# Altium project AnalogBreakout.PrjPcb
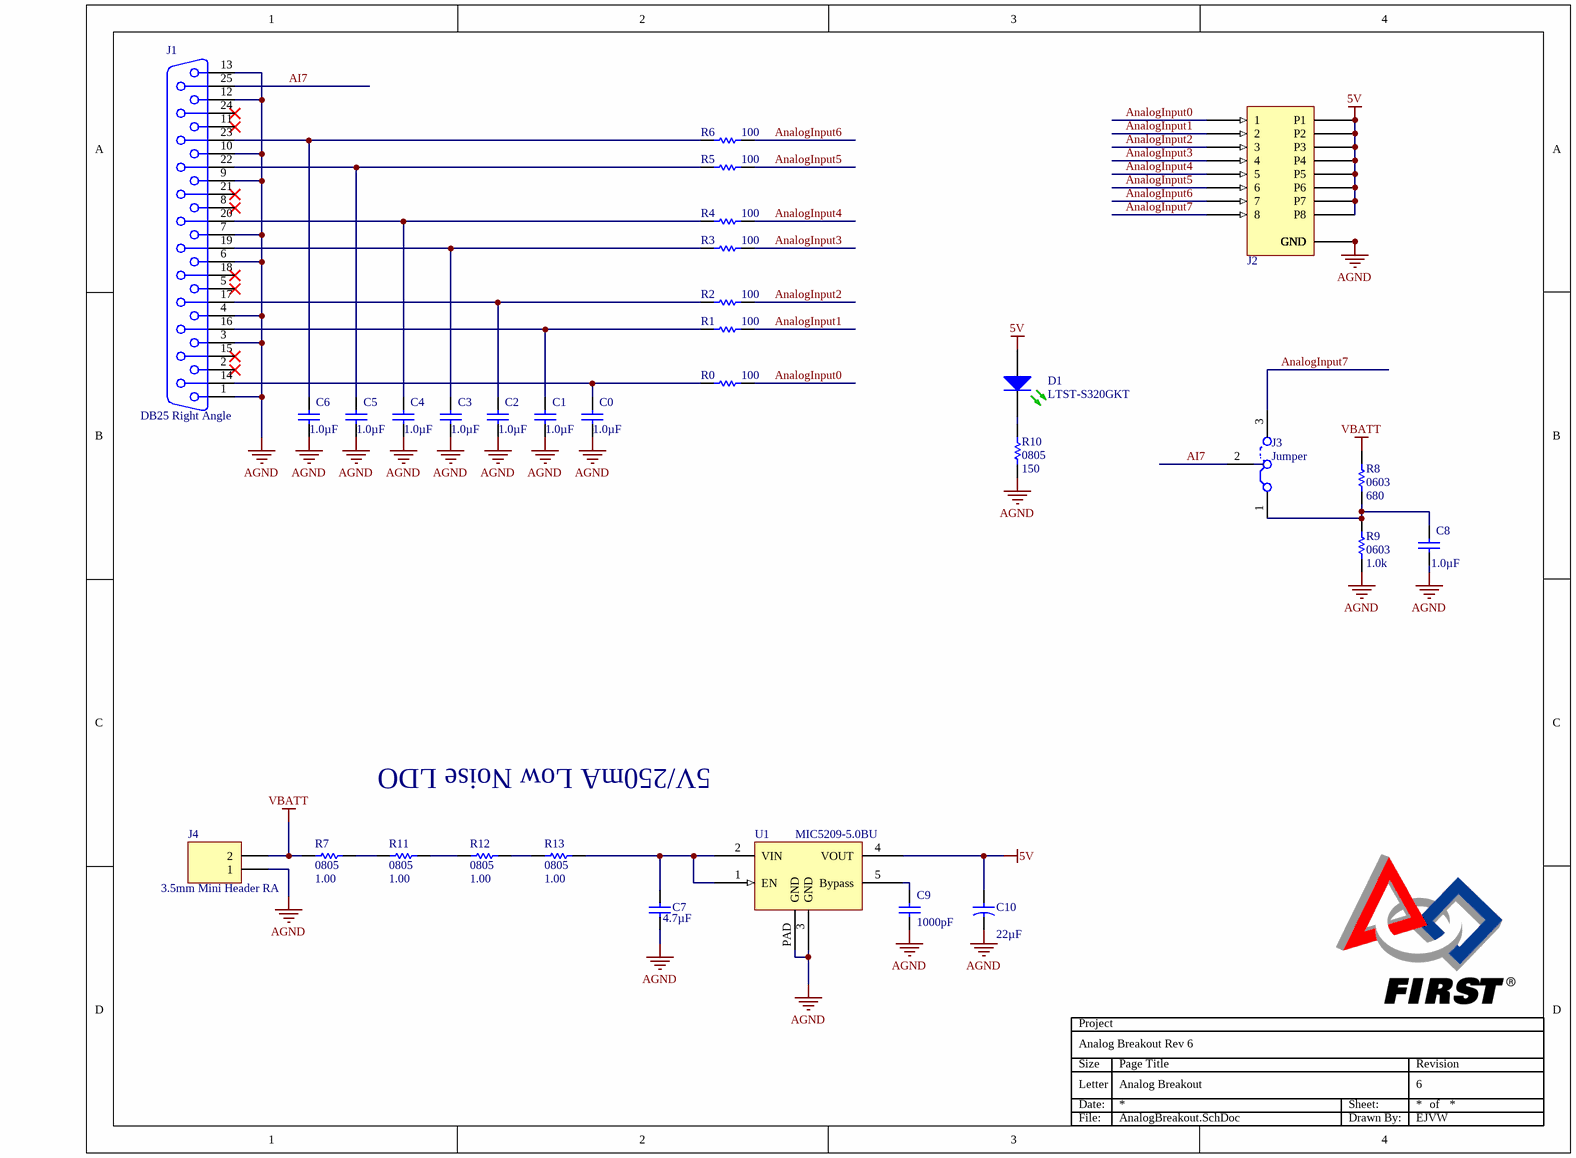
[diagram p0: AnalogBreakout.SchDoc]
ProjectTitle: Analog Breakout Rev 6
2 sheets, 31 parts. Net scope: global (net labels, ports and power ports of the same name join across sheets).
Board file: AnalogBreakout.PcbDoc
Sheets:
  AnalogBreakout.SchDoc
  Title.SchDoc

## Sheet AnalogBreakout.SchDoc: Analog Breakout
size Letter; DrawnBy: EJVW; Revision: 6

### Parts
C0  value 1.0µF  [C0603_C]  (hidden comment: 1.0 uF 0603)
C1  value 1.0µF  [C0603_C]  (hidden comment: 1.0 uF 0603)
C2  value 1.0µF  [C0603_C]  (hidden comment: 1.0 uF 0603)
C3  value 1.0µF  [C0603_C]  (hidden comment: 1.0 uF 0603)
C4  value 1.0µF  [C0603_C]  (hidden comment: 1.0 uF 0603)
C5  value 1.0µF  [C0603_C]  (hidden comment: 1.0 uF 0603)
C6  value 1.0µF  [C0603_C]  (hidden comment: 1.0 uF 0603)
C7  value 4.7µF  [C0805_C]  (hidden comment: 4.7uF 0805 25V X5R)
C8  value 1.0µF  [C0603_C]  (hidden comment: 1.0 uF 0603)
C9  value 1000pF  [C0603_C]  (hidden comment: 1000 pF 0603)
C10  value 22µF  [SMT-CAN Panasonic C]  (hidden comment: 22uF SMT 25V Elecrolytic)
D1  LTST-S320GKT  [LED1208RA LiteOn]
J1  DB25 Right Angle  [DB25 - RA]
J2  PWM_Header x8 RA  [H100P3x8RA]  (value not drawn)
J3  Jumper  [J100P3]
J4  3.5mm Mini Header RA  [WAGO 734-162]
R0  value 100  [R0603_C]  (hidden comment: 100 ohm 0603 1%)
R1  value 100  [R0603_C]  (hidden comment: 100 ohm 0603 1%)
R2  value 100  [R0603_C]  (hidden comment: 100 ohm 0603 1%)
R3  value 100  [R0603_C]  (hidden comment: 100 ohm 0603 1%)
R4  value 100  [R0603_C]  (hidden comment: 100 ohm 0603 1%)
R5  value 100  [R0603_C]  (hidden comment: 100 ohm 0603 1%)
R6  value 100  [R0603_C]  (hidden comment: 100 ohm 0603 1%)
R7  value 1.00  Footprint: 0805  [R0805_M]  (hidden comment: 1.00 ohm 0805 1%)
R8  value 680  Footprint: 0603  [R0603_C]  (hidden comment: 680 ohm 0805 1%)
R9  value 1.0k  Footprint: 0603  [R0603_C]  (hidden comment: 1.0k ohm 0603 1%)
R10  value 150  Footprint: 0805  [R0805_M]  (hidden comment: 150 ohm 0805 1%)
R11  value 1.00  Footprint: 0805  [R0805_M]  (hidden comment: 1.00 ohm 0805 1%)
R12  value 1.00  Footprint: 0805  [R0805_M]  (hidden comment: 1.00 ohm 0805 1%)
R13  value 1.00  Footprint: 0805  [R0805_M]  (hidden comment: 1.00 ohm 0805 1%)
U1  MIC5209-5.0BU  [TO-263-5]

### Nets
5V: C10.+ D1.A J2.2(P1) J2.5(P2) J2.8(P3) J2.11(P4) J2.14(P5) J2.17(P6) J2.20(P7) J2.23(P8) U1.4(VOUT)
AGND: C0.1 C1.1 C2.1 C3.1 C4.1 C5.1 C6.2 C7.1 C8.1 C9.1 C10.- J1.1 J1.3 J1.4 J1.6 J1.7 J1.9 J1.10 J1.12 J1.13 J2.3(GND) J2.6(GND) J2.9(GND) J2.12(GND) J2.15(GND) J2.18(GND) J2.21(GND) J2.24(GND) J4.1 R9.1 R10.1 U1.3(GND) U1.PAD(GND)
VBATT: J4.2 R7.1 R8.2
AI7: J1.25 J3.2
AnalogInput0: J2.1 R0.2
AnalogInput1: J2.4(2) R1.2
AnalogInput2: J2.7(3) R2.2
AnalogInput3: J2.10(4) R3.2
AnalogInput4: J2.13(5) R4.2
AnalogInput5: J2.16(6) R5.2
AnalogInput6: J2.19(7) R6.2
AnalogInput7: J2.22(8) J3.3
NetC0_2: C0.2 J1.14 R0.1
NetC1_2: C1.2 J1.16 R1.1
NetC2_2: C2.2 J1.17 R2.1
NetC3_2: C3.2 J1.19 R3.1
NetC4_2: C4.2 J1.20 R4.1
NetC5_2: C5.2 J1.22 R5.1
NetC6_1: C6.1 J1.23 R6.1
NetC7_2: C7.2 R13.2 U1.1(EN) U1.2(VIN)
NetC8_2: C8.2 J3.1 R8.1 R9.2
NetC9_2: C9.2 U1.5(Bypass)
NetD1_K: D1.K R10.2
NetR7_2: R7.2 R11.1
NetR11_2: R11.2 R12.1
NetR12_2: R12.2 R13.1

Not connected (* = marked no-connect by the designer): J1 2* 5* 8* 11* 15* 18* 21* 24*

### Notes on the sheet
- 5V/250mA Low Noise LDO

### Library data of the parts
C0-C6 C8 = 1.0µF 0603 10V: Capacitor; MFG: Kemet; MFG_PN: C0603C105K8PACTU; DIST: DigiKey; DIST_PN: 399-3118-1-ND; Tolerance: ±10%; Temperature Coefficient: X5R; Voltage: 10
C7 = 4.7uF 0805 25V X5R: CERAMIC 4.7uF 25V X5R 0805; MFG: Panasonic - ECG; MFG_PN: ECJ-2FB1E475M; DIST: DigiKey; DIST_PN: PCC2321CT-ND; Tolerance: ±20%; Voltage: 25; Checked: SCH 3/2/2008; Cost (1000): 0.08988
C9 = 1000 pF 0603 50V: Capacitor; MFG: Kemet; MFG_PN: C0603C102K5RACTU; DIST: DigiKey; DIST_PN: 399-1082-1-ND; Tolerance: ±10%; Temperature Coefficient: C0G, NP0 (COG,NPO); Voltage: 50
C10 = 22uF SMT 25V Elecrolytic: MFG: Panasonic - ECG; MFG_PN: EEV-FK1E220R; DIST: DigiKey; DIST_PN: PCE3404CT-ND; Tolerance: ±20%; Voltage: 25; ESR: 0.7; Cost (1000): 0.16950; Ripple Current (Amps): 0.160; Max Temperature (C): 105; Cost (MOQ): 0.28800
D1 = LTST-S320GKT: Green 1208RA 20mA 2V 10mcd; MFG: Panasonic - SSG; DIST: DIGIKEY; DIST_PN: 160-1206-1-ND; I_F: 20; Luminous Intensity: 12mcd; Maximum Continuous Current: 30; V_F: 2.1; Viewing Angle: 130; Cost (1000): 0.08000
J1 = DB25F RA Unthreaded: DB25F RA Unthreaded .318"; DIST: DigiKey; DIST_PN: 182-725FE-ND; MFG: Norcomp Inc.; MFG_PN: 182-025-213R161
J2 = PWM_Header x8 RA: PWM Header x8 RA; MFG: Samtec; MFG_PN: TSW-108-08-T-T-LA
J3 = Jumper 3pos 100mil_RA: Selection Jumper, Right Angle; DIST: Samtec; DIST_PN: TSW-103-08-T-S-RA
J4 = WAGO 734-162: 3.5mm Header Protected against Mismating; MFG: WAGO; Current Rating: 10 A; Mates With: 734-102/037-000
R0-R6 = 100 ohm 0603 1%: MFG: Rohm; MFG_PN: MCR03EZPFX1000; DIST: DigiKey; DIST_PN: RHM100HCT-ND; Power: 0.1; Cost (1000): 0.01595; Cost (MOQ): 0.076; BOM Note: Generic - May be replaced by equal or better part
R7 R11-R13 = 1.00 ohm 0805 1%: MFG: Rohm; MFG_PN: MCR10EZHFL1R00; DIST: DigiKey; DIST_PN: RHM1.00CCT-ND; Power: 0.25W, 1/4W; Cost (1000): 0.06830; Cost (MOQ): 0.14100
R8 = 680 ohm 0603 1%: MFG: Rohm; MFG_PN: MCR03EZPFX6800; DIST: DigiKey; DIST_PN: RHM680HCT-ND; Power: 0.1; Cost (1000): 0.01595; Cost (MOQ): 0.076; BOM Note: Generic - May be replaced by equal or better part
R9 = 1.0k ohm 0603 1%: MFG: Rohm; MFG_PN: MCR03EZPFX1001; DIST: DigiKey; DIST_PN: RHM1.00KHCT-ND; Power: 0.1; Cost (1000): 0.01595; Cost (MOQ): 0.076; BOM Note: Generic - May be replaced by equal or better part
R10 = 150 ohm 0805 1%: MFG: Rohm; MFG_PN: MCR10EZPF1500; DIST: DigiKey; DIST_PN: RHM150CRCT-ND; Power: 0.125W, 1/8W; Cost (1000): 0.01795; Cost (MOQ): 0.03700; BOM Note: Generic
U1 = MIC5209-5.0BU: 5.0V 500mA Low-Noise LDO; Current Limit: 0.500; DIST: NU Horizons; DIST_PN: MIC5209-5.0BU TR; MFG: Micrel; Voltage Output: 5.0; Maximum Drop Out Voltage: 0.600; Max Voltage: 16.0V; Topology: Linear (Fixed); Cost (1000): 1.2900

## Sheet Title.SchDoc
size Letter; SheetNumber: 1
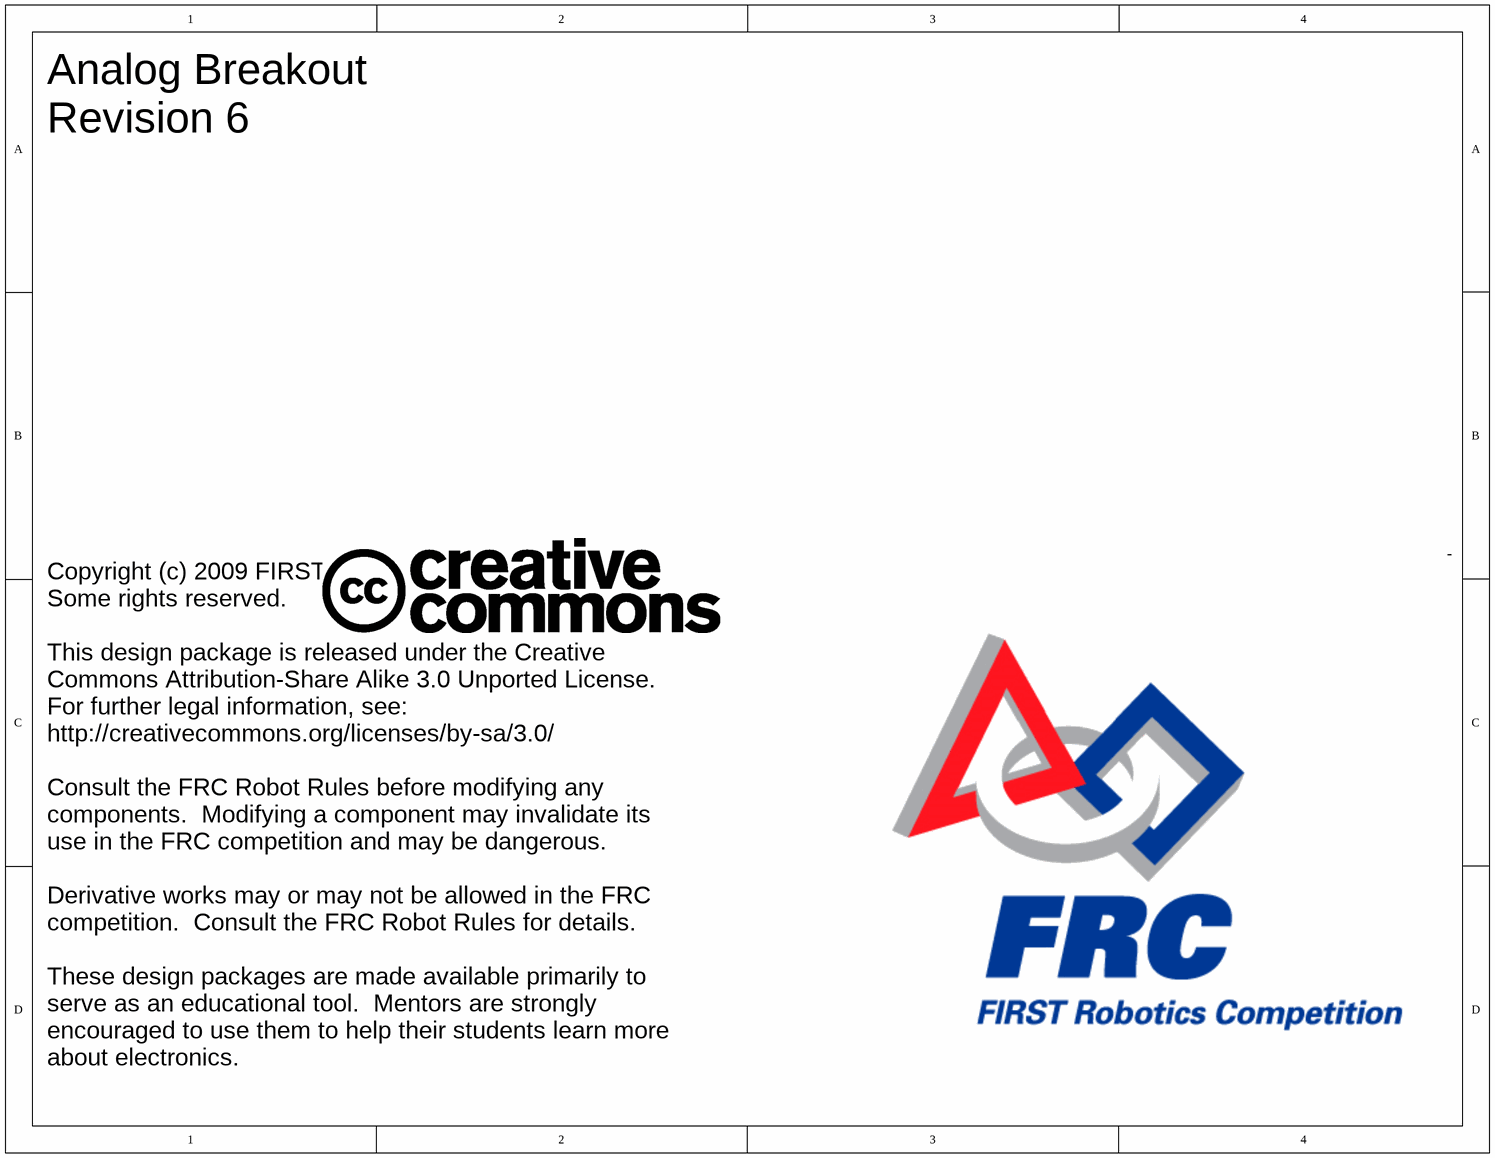
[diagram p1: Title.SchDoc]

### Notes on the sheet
- Analog Breakout
  Revision 6
- Copyright (c) 2009 FIRST
  Some rights reserved.
  This design package is released under the Creative Commons Attribution-Share Alike 3.0 Unported License.  For further legal information, see:
  http://creativecommons.org/licenses/by-sa/3.0/
  Consult the FRC Robot Rules before modifying any components.  Modifying a component may invalidate its use in the FRC competition and may be dangerous.
  Derivative works may or may not be allowed in the FRC competition.  Consult the FRC Robot Rules for details.
  These design packages are made available primarily to serve as an educational tool.  Mentors are strongly encouraged to use them to help their students learn more about electronics.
